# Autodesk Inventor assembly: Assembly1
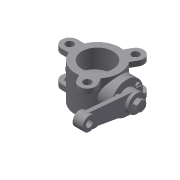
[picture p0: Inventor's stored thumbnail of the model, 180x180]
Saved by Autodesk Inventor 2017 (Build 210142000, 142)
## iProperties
Created: 2016-07
Part Number: Assembly1
Document SubType Name: Assembly
Designer: Sandeep
Author: Sandeep
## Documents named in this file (9)
- D:\KAVITA\Autodesk Inventor_2017_Project\Part's File\Inventor_2016_tut\c09_Inv_tut_2016\c09_tut01_inv\Butterfly Valve\Assembly1.iam
- D:\KAVITA\Autodesk Inventor_2017_Project\Part's File\Inventor_2016_tut\c09_Inv_tut_2016\c09_tut01_inv\Butterfly Valve\Body.ipt
- D:\KAVITA\Autodesk Inventor_2017_Project\Part's File\Inventor_2016_tut\c09_Inv_tut_2016\c09_tut01_inv\Butterfly Valve\shaft1.ipt
- D:\KAVITA\Autodesk Inventor_2017_Project\Part's File\Inventor_2016_tut\c09_Inv_tut_2016\c09_tut01_inv\Butterfly Valve\Arm1.ipt
- D:\KAVITA\Autodesk Inventor_2017_Project\Part's File\Inventor_2016_tut\c09_Inv_tut_2016\c09_tut01_inv\Butterfly Valve\Retainer.ipt
- D:\KAVITA\Autodesk Inventor_2017_Project\Part's File\Inventor_2016_tut\c09_Inv_tut_2016\c09_tut01_inv\Butterfly Valve\scew1.ipt
- D:\KAVITA\Autodesk Inventor_2017_Project\Part's File\Inventor_2016_tut\c09_Inv_tut_2016\c09_tut01_inv\Butterfly Valve\Plate.ipt
- D:\KAVITA\Autodesk Inventor_2017_Project\Part's File\Inventor_2016_tut\c09_Inv_tut_2016\c09_tut01_inv\Butterfly Valve\Screw.ipt
- D:\KAVITA\Autodesk Inventor_2017_Project\Part's File\Inventor_2016_tut\c09_Inv_tut_2016\c09_tut01_inv\Butterfly Valve\Nut.ipt
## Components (11 placed, 8 different names)
1. Body:2 — Mate:1, Insert:2, Insert:3, Angle:3, Insert:12
2. shaft1:1 — Angle:2, Angle:3, Insert:5, Insert:6, Insert:12, Insert:13
3. Retainer:1 — Mate:1, Insert:2, Insert:3, Insert:4, Angle:1, Insert:9, Insert:10, Insert:11
4. Arm1:2 — Insert:4, Angle:1, Angle:2
5. scew1:1 — Insert:7
6. scew1:2 — Insert:8
7. Plate:1 — Insert:5, Insert:6, Insert:7, Insert:8
8. Screw:1 — Insert:9
9. Screw:2 — Insert:10
10. Screw:3 — Insert:11
11. Nut:1 — Insert:13
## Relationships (16: Insert 12, Angle 3, Mate 1)
- Mate:1: Body:2 ↔ Retainer:1
- Insert:2: Body:2 ↔ Retainer:1
- Insert:3: Body:2 ↔ Retainer:1
- Insert:4: Retainer:1 ↔ Arm1:2
- Angle:1: Retainer:1 ↔ Arm1:2
- Angle:2: shaft1:1 ↔ Arm1:2
- Angle:3: Body:2 ↔ shaft1:1
- Insert:5: shaft1:1 ↔ Plate:1
- Insert:6: shaft1:1 ↔ Plate:1
- Insert:7: scew1:1 ↔ Plate:1
- Insert:8: scew1:2 ↔ Plate:1
- Insert:9: Retainer:1 ↔ Screw:1
- Insert:10: Retainer:1 ↔ Screw:2
- Insert:11: Retainer:1 ↔ Screw:3
- Insert:12: Body:2 ↔ shaft1:1
- Insert:13: shaft1:1 ↔ Nut:1
